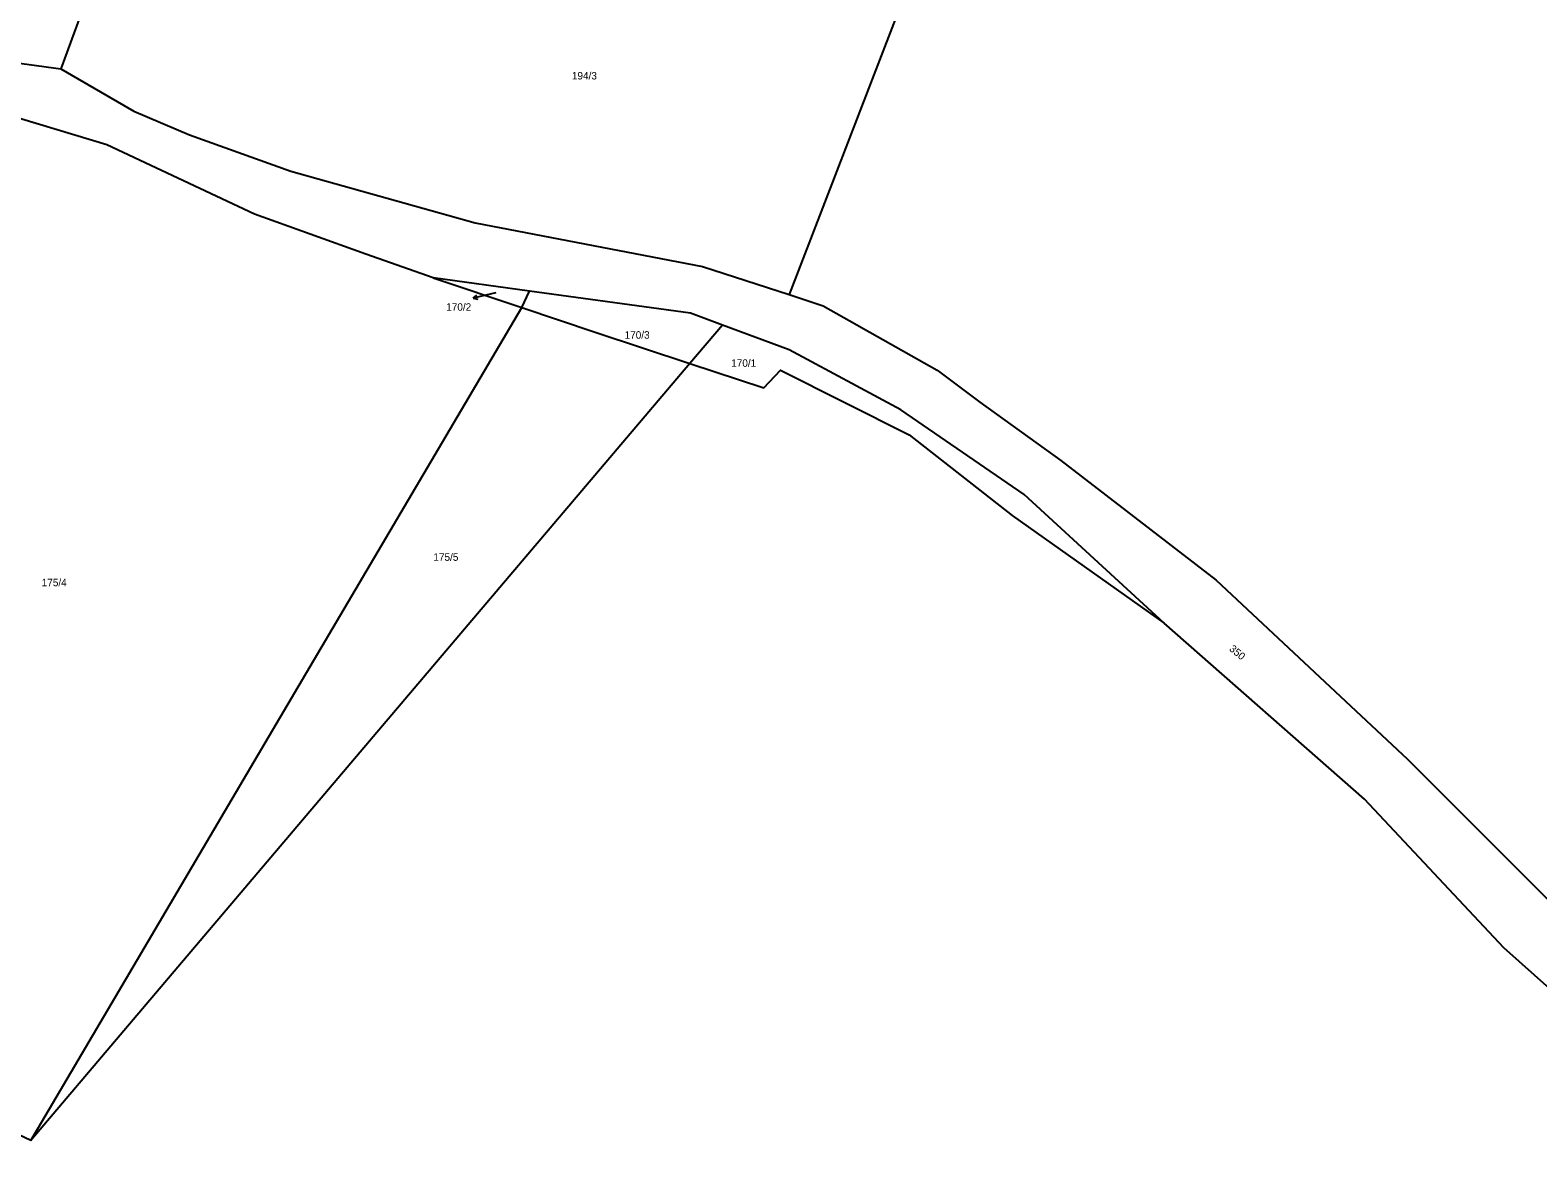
# Model space of a CAD drawing. Extents: x -880531 to -877616, y -1023932 to -1021350.
# Drawn here: x -878520.6 to -878177.4, y -1022969 to -1022709.3 of the extents above; entities that cross this region are included whole.
import ezdxf

# ---------------------------------------------------------------- set-up
doc = ezdxf.new("R2010")
doc.units = 0
for name, color, linetype in [('Hranice parcel', 7, 'Continuous'), ('Parcelní čísla', 7, 'Continuous'), ('Pop  PČ popisy', 7, 'Continuous')]:
    doc.layers.add(name, color=color, linetype=linetype)

msp = doc.modelspace()

# ---------------------------------------------------------------- linework, layer by layer
at = {"layer": 'Hranice parcel'}
for p, q in [((-878300.59, -1022646.88), (-878347.85, -1022769.53)), ((-878503.14, -1022689.72), (-878513.6, -1022718.13)), ((-878428.81, -1022765.67), (-878408.66, -1022772.47)), ((-878406.89, -1022768.71), (-878428.81, -1022765.67)), ((-878408.66, -1022772.47), (-878406.89, -1022768.71)), ((-878363.03, -1022776.44), (-878370.46, -1022785.21)), ((-878520.42, -1022962.14), (-878650.42, -1022901.16))]:
    msp.add_line(p, q, dxfattribs=at)
for points in [[(-878428.81, -1022765.67), (-878444.18, -1022760.32), (-878469.54, -1022751.18), (-878503.13, -1022735.42), (-878534.57, -1022725.92), (-878568.59, -1022718.45), (-878589.15, -1022713.89)], [(-878541.54, -1022714.07), (-878529.74, -1022715.93), (-878513.6, -1022718.13)], [(-878513.6, -1022718.13), (-878496.99, -1022727.75), (-878484.3, -1022733.13), (-878461.2, -1022741.4), (-878419.3, -1022753.21), (-878367.51, -1022763.13), (-878347.85, -1022769.53)], [(-878363.03, -1022776.44), (-878370.25, -1022773.78), (-878406.89, -1022768.71)], [(-878520.42, -1022962.14), (-878464.55, -1022867.31), (-878408.66, -1022772.47)], [(-878408.66, -1022772.47), (-878392.01, -1022778.1), (-878370.46, -1022785.21)], [(-878347.85, -1022769.53), (-878340.08, -1022772.06), (-878314.12, -1022786.74), (-878304.44, -1022794.02), (-878285.98, -1022807.27), (-878250.6, -1022834.52), (-878207.11, -1022875.3), (-878172.27, -1022910.11), (-878140.8, -1022940.6), (-878089.05, -1022975.4), (-878018.43, -1023024.57), (-877994.66, -1023044.33), (-877959.43, -1023078.68), (-877895.65, -1023138.67), (-877846.1, -1023187.34), (-877827.04, -1023210.17), (-877810.32, -1023234.77), (-877793.71, -1023263.48)], [(-878262.44, -1022844.37), (-878294.35, -1022815.03), (-878322.39, -1022795.74), (-878347.81, -1022782.06), (-878363.03, -1022776.44)], [(-878370.46, -1022785.21), (-878445.44, -1022873.68), (-878520.42, -1022962.14)], [(-878370.46, -1022785.21), (-878353.61, -1022790.76), (-878349.81, -1022786.76), (-878320.48, -1022801.45), (-878297.05, -1022819.79), (-878262.44, -1022844.37)], [(-877780.67, -1023314.89), (-877785.52, -1023301.59), (-877820.27, -1023240.12), (-877836.64, -1023216.31), (-877856.74, -1023193.96), (-877904.17, -1023147.51), (-877968.01, -1023086.79), (-878004.38, -1023051.82), (-878026.11, -1023034.14), (-878098.6, -1022986.3), (-878150.98, -1022948.79), (-878185.16, -1022918.23), (-878216.86, -1022884.4), (-878262.44, -1022844.37)]]:
    msp.add_lwpolyline(points, dxfattribs=at)
at = {"layer": 'Pop  PČ popisy'}
for p, q in [((-878414.59, -1022769.12), (-878416.83, -1022769.65)), ((-878419.754, -1022770.325), (-878418.891, -1022769.612)), ((-878416.83, -1022769.65), (-878419.754, -1022770.325)), ((-878419.754, -1022770.325), (-878418.666, -1022770.588))]:
    msp.add_line(p, q, dxfattribs=at)

# ---------------------------------------------------------------- texts
at = {"layer": 'Parcelní čísla'}
for s, p in [('194/3', (-878397.27, -1022720.53)), ('170/2', (-878425.871, -1022773.188)), ('170/3', (-878385.27, -1022779.55)), ('170/1', (-878361.01, -1022785.96)), ('175/5', (-878428.79, -1022830.13)), ('175/4', (-878517.93, -1022835.92))]:
    msp.add_text(s, height=1.7, dxfattribs=at).set_placement(p)
msp.add_text('350', height=1.7, rotation=320, dxfattribs=at).set_placement((-878247.806, -1022850.421))

doc.saveas('drawing.dxf')
